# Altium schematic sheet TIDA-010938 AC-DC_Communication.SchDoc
size 431 x 279 mm; Date: Not shown in title block; ApprovedBy: Not shown in title block; CheckedBy: Not shown in title block; Author: Not shown in title block; CompanyName: Not shown in title block; Engineer: Not shown in title block; Organization: Not shown in title block; Address1: Not shown in title block; Address2: Not shown in title block; Address3: Not shown in title block; Address4: Not shown in title block; DocumentNumber: 10; Revision: Use project parameter SCH_Rev; SheetNumber: 10; SheetTotal: 11; PageSetup: Record=PageOptions¦CenterHorizontal=True¦CenterVertical=True¦PrintScale=1.00¦XCorrection=1.00¦YCorrection=1.00¦PrintKind=0¦BorderSize=5000000¦LeftOffset=0¦BottomOffset=0¦Orientation=2¦PaperLength=1000¦PaperWidth=1000¦Scale=100¦PaperSource=15¦PrintQuality=600¦MediaType=1¦DitherType=10¦PaperKind=Letter¦PrintScaleMode=1
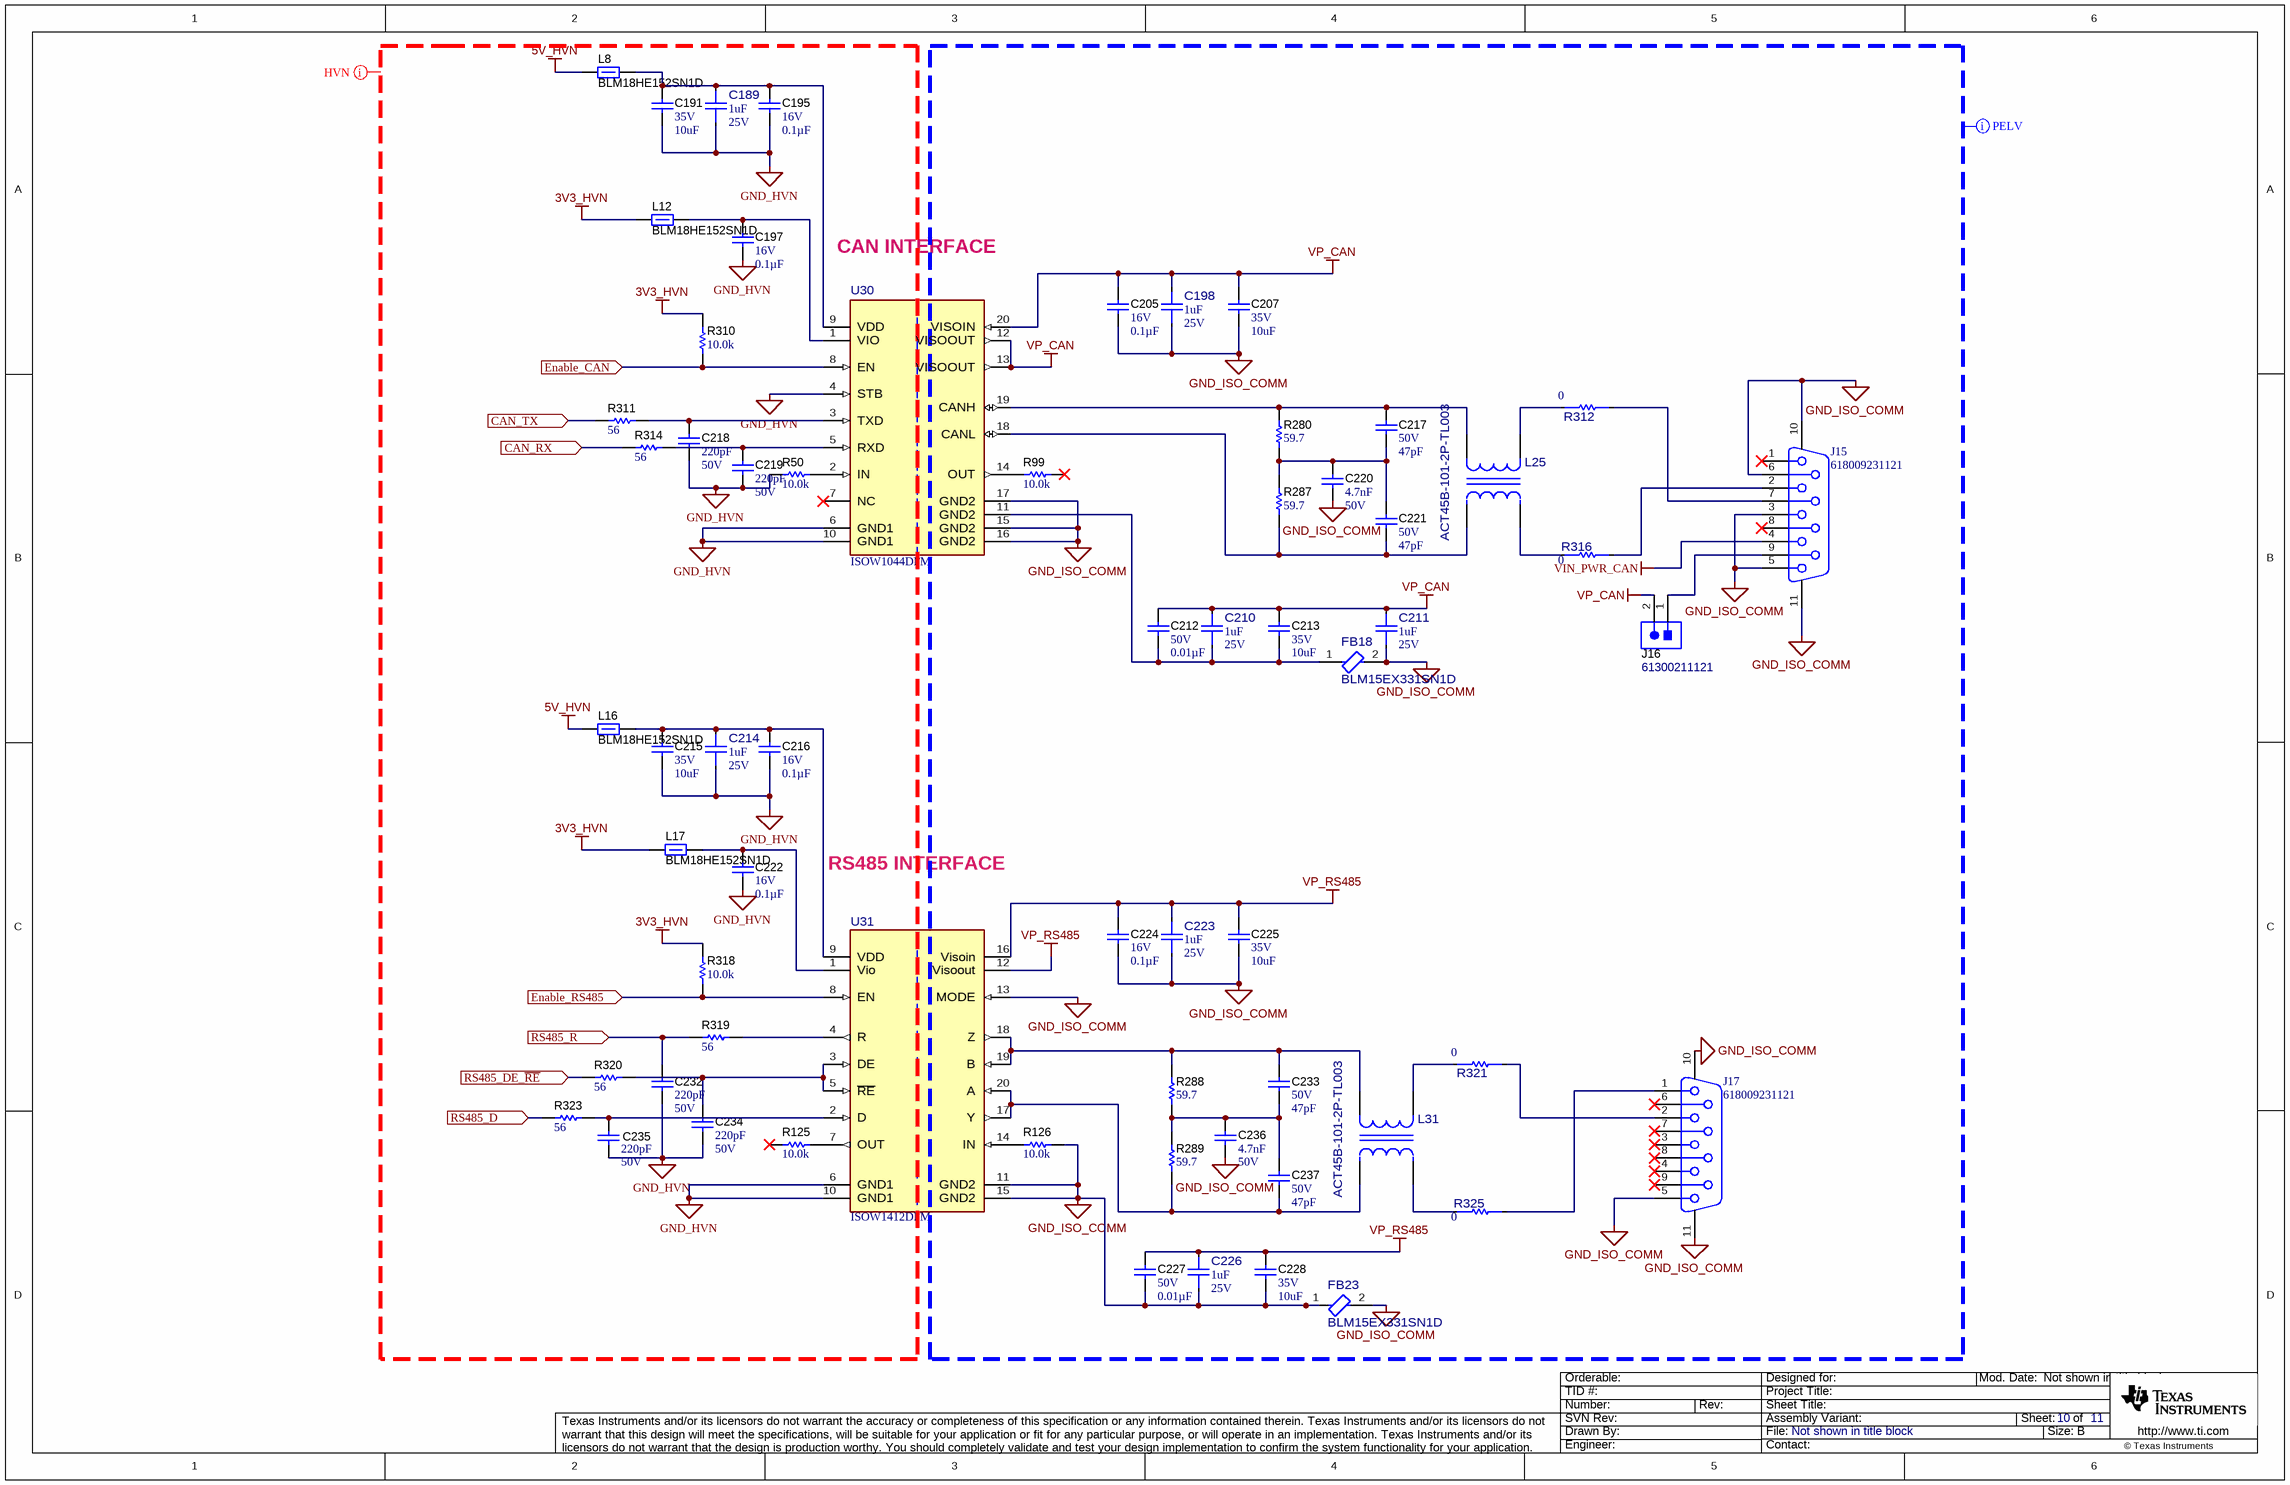
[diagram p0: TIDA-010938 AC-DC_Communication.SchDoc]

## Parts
C189  ValueDisplayed: 1uF  VDC_V: 25V  [FP-CL10A105KA8NNNC_0603-IPC_C]  (hidden comment: CL10A105KA8NNNC)
C191  VDC_V: 35V  ValueDisplayed: 10uF  [0805_HV]  (hidden comment: GRM21BR6YA106KE43L)
C195  VDC_V: 16V  ValueDisplayed: 0.1µF  [0402]  (hidden comment: CL05B104KO5NNNC)
C197  VDC_V: 16V  ValueDisplayed: 0.1µF  [0402]  (hidden comment: CL05B104KO5NNNC)
C198  ValueDisplayed: 1uF  VDC_V: 25V  [FP-CL10A105KA8NNNC_0603-IPC_C]  (hidden comment: CL10A105KA8NNNC)
C205  VDC_V: 16V  ValueDisplayed: 0.1µF  [0402]  (hidden comment: CL05B104KO5NNNC)
C207  VDC_V: 35V  ValueDisplayed: 10uF  [0805_HV]  (hidden comment: GRM21BR6YA106KE43L)
C210  ValueDisplayed: 1uF  VDC_V: 25V  [FP-CL10A105KA8NNNC_0603-IPC_C]  (hidden comment: CL10A105KA8NNNC)
C211  ValueDisplayed: 1uF  VDC_V: 25V  [FP-CL10A105KA8NNNC_0603-IPC_C]  (hidden comment: CL10A105KA8NNNC)
C212  VDC_V: 50V  ValueDisplayed: 0.01µF  [0402]  (hidden comment: 0402B103K500CT)
C213  VDC_V: 35V  ValueDisplayed: 10uF  [0805_HV]  (hidden comment: GRM21BR6YA106KE43L)
C214  ValueDisplayed: 1uF  VDC_V: 25V  [FP-CL10A105KA8NNNC_0603-IPC_C]  (hidden comment: CL10A105KA8NNNC)
C215  VDC_V: 35V  ValueDisplayed: 10uF  [0805_HV]  (hidden comment: GRM21BR6YA106KE43L)
C216  VDC_V: 16V  ValueDisplayed: 0.1µF  [0402]  (hidden comment: CL05B104KO5NNNC)
C217  VDC_V: 50V  ValueDisplayed: 47pF  [0603]  (hidden comment: GRM1885C1H470JA01D)
C218  Cap_F: 220pF  VDC_V: 50V  [0603]  (hidden comment: GRM188R71H221KA01D)
C219  Cap_F: 220pF  VDC_V: 50V  [0603]  (hidden comment: GRM188R71H221KA01D)
C220  Cap_F: 4.7nF  VDC_V: 50V  [0603]  (hidden comment: C0603X472K5RACTU)
C221  VDC_V: 50V  ValueDisplayed: 47pF  [0603]  (hidden comment: GRM1885C1H470JA01D)
C222  VDC_V: 16V  ValueDisplayed: 0.1µF  [0402]  (hidden comment: CL05B104KO5NNNC)
C223  ValueDisplayed: 1uF  VDC_V: 25V  [FP-CL10A105KA8NNNC_0603-IPC_C]  (hidden comment: CL10A105KA8NNNC)
C224  VDC_V: 16V  ValueDisplayed: 0.1µF  [0402]  (hidden comment: CL05B104KO5NNNC)
C225  VDC_V: 35V  ValueDisplayed: 10uF  [0805_HV]  (hidden comment: GRM21BR6YA106KE43L)
C226  ValueDisplayed: 1uF  VDC_V: 25V  [FP-CL10A105KA8NNNC_0603-IPC_C]  (hidden comment: CL10A105KA8NNNC)
C227  VDC_V: 50V  ValueDisplayed: 0.01µF  [0402]  (hidden comment: 0402B103K500CT)
C228  VDC_V: 35V  ValueDisplayed: 10uF  [0805_HV]  (hidden comment: GRM21BR6YA106KE43L)
C232  Cap_F: 220pF  VDC_V: 50V  [0603]  (hidden comment: GRM188R71H221KA01D)
C233  VDC_V: 50V  ValueDisplayed: 47pF  [0603]  (hidden comment: GRM1885C1H470JA01D)
C234  Cap_F: 220pF  VDC_V: 50V  [0603]  (hidden comment: GRM188R71H221KA01D)
C235  Cap_F: 220pF  VDC_V: 50V  [0603]  (hidden comment: GRM188R71H221KA01D)
C236  Cap_F: 4.7nF  VDC_V: 50V  [0603]  (hidden comment: C0603X472K5RACTU)
C237  VDC_V: 50V  ValueDisplayed: 47pF  [0603]  (hidden comment: GRM1885C1H470JA01D)
FB18  BLM15EX331SN1D  [FP-BLM15EX331SN1D_0402-MFG]
FB23  BLM15EX331SN1D  [FP-BLM15EX331SN1D_0402-MFG]
J15  618009231121  [Wurth_618009231121]
J16  61300211121  [WURTH_61300211121]
J17  618009231121  [Wurth_618009231121]
L8  BLM18HE152SN1D  [0603]
L12  BLM18HE152SN1D  [0603]
L16  BLM18HE152SN1D  [0603]
L17  BLM18HE152SN1D  [0603]
L25  ACT45B-101-2P-TL003  [FP-ACT45B-101-2P-TL003_SMT_4MM5_3MM2-MFG]
L31  ACT45B-101-2P-TL003  [FP-ACT45B-101-2P-TL003_SMT_4MM5_3MM2-MFG]
R50  ValueDisplayed: 10.0k  [0603]  (hidden comment: RG1608P-103-B-T5)
R99  ValueDisplayed: 10.0k  [0603]  (hidden comment: RG1608P-103-B-T5)
R125  ValueDisplayed: 10.0k  [0603]  (hidden comment: RG1608P-103-B-T5)
R126  ValueDisplayed: 10.0k  [0603]  (hidden comment: RG1608P-103-B-T5)
R280  ValueDisplayed: 59.7  [0603]  (hidden comment: RT0603DRE0759R7L)
R287  ValueDisplayed: 59.7  [0603]  (hidden comment: RT0603DRE0759R7L)
R288  ValueDisplayed: 59.7  [0603]  (hidden comment: RT0603DRE0759R7L)
R289  ValueDisplayed: 59.7  [0603]  (hidden comment: RT0603DRE0759R7L)
R310  ValueDisplayed: 10.0k  [0603]  (hidden comment: RG1608P-103-B-T5)
R311  ValueDisplayed: 56  [0603]  (hidden comment: RG1608P-560-B-T5)
R312  Res_ohm: 0  [FP-RMCF0805ZT0R00_0805-MFG]  (hidden comment: RMCF0805ZT0R00)
R314  ValueDisplayed: 56  [0603]  (hidden comment: RG1608P-560-B-T5)
R316  Res_ohm: 0  [FP-RMCF0805ZT0R00_0805-MFG]  (hidden comment: RMCF0805ZT0R00)
R318  ValueDisplayed: 10.0k  [0603]  (hidden comment: RG1608P-103-B-T5)
R319  ValueDisplayed: 56  [0603]  (hidden comment: RG1608P-560-B-T5)
R320  ValueDisplayed: 56  [0603]  (hidden comment: RG1608P-560-B-T5)
R321  Res_ohm: 0  [FP-RMCF0805ZT0R00_0805-MFG]  (hidden comment: RMCF0805ZT0R00)
R323  ValueDisplayed: 56  [0603]  (hidden comment: RG1608P-560-B-T5)
R325  Res_ohm: 0  [FP-RMCF0805ZT0R00_0805-MFG]  (hidden comment: RMCF0805ZT0R00)
U30  ISOW1044DFM  [DFM0020A-MFG]
U31  ISOW1412DFM  [DFM0020A-MFG]

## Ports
CAN_RX (in), CAN_TX (in), Enable_CAN (in), Enable_RS485 (in), RS485_D (in), RS485_DE_~{RE} (in), RS485_R (in)

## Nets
3V3_HVN: L12.1 L17.1 R310.2 R318.2
5V_HVN: L8.1 L16.1
GND_HVN: C189.1 C191.2 C195.2 C197.2 C214.1 C215.2 C216.2 C218.1 C219.1 C222.2 C232.1 C234.1 C235.1 R50.2 U30.4(STB) U30.6(GND1) U30.10(GND1) U31.6(GND1) U31.10(GND1)
GND_ISO_COMM: C198.1 C205.2 C207.2 C211.1 C220.1 C223.1 C224.2 C225.2 C226.1 C227.2 C228.2 C236.1 FB18.2 FB23.1 FB23.2 J15.3 J15.5 J15.6 J15.10 J15.11 J17.5 J17.10 J17.11 R126.1 U30.15(GND2) U30.16(GND2) U30.17(GND2) U31.11(GND2) U31.13(MODE) U31.15(GND2)
VIN_PWR_CAN: J15.4
VP_CAN: C198.2 C205.1 C207.1 C210.2 C211.2 C212.1 C213.1 J16.2 U30.12(VISOOUT) U30.13(VISOOUT) U30.20(VISOIN)
VP_RS485: C223.2 C224.1 C225.1 C226.2 C227.1 C228.1 U31.12(Visoout) U31.16(Visoin)
CAN_RX: R314.1 ; port CAN_RX
CAN_TX: R311.1 ; port CAN_TX
Enable_CAN: R310.1 U30.8(EN) ; port Enable_CAN
Enable_RS485: R318.1 U31.8(EN) ; port Enable_RS485
RS485_D: R323.1 ; port RS485_D
RS485_DE_~{RE}: R320.1 ; port RS485_DE_~{RE}
RS485_R: C232.2 R319.1 ; port RS485_R
NetC189_2: C189.2 C191.1 C195.1 L8.2 U30.9(VDD)
NetC197_1: C197.1 L12.2 U30.1(VIO)
NetC210_1: C210.1 C212.2 C213.2 FB18.1 U30.11(GND2)
NetC214_2: C214.2 C215.1 C216.1 L16.2 U31.9(VDD)
NetC217_1: C217.1 C220.2 C221.2 R280.1 R287.2
NetC217_2: C217.2 L25.1 R280.2 U30.19(CANH)
NetC218_2: C218.2 R311.2 U30.3(TXD)
NetC219_2: C219.2 R314.2 U30.5(RXD)
NetC221_1: C221.1 L25.2 R287.1 U30.18(CANL)
NetC222_1: C222.1 L17.2 U31.1(Vio)
NetC233_1: C233.1 C236.2 C237.2 R288.1 R289.2
NetC233_2: C233.2 L31.1 R288.2 U31.18(Z) U31.19(B)
NetC234_2: C234.2 R320.2 U31.3(DE) U31.5(~{RE})
NetC235_2: C235.2 R323.2 U31.2(D)
NetC237_1: C237.1 L31.2 R289.1 U31.17(Y) U31.20(A)
NetJ15_2: J15.2 R316.2
NetJ15_7: J15.7 R312.2
NetJ15_9: J15.9 J16.1
NetJ17_1: J17.1 R325.2
NetJ17_2: J17.2 R321.2
NetL25_3: L25.3 R316.1
NetL25_4: L25.4 R312.1
NetL31_3: L31.3 R325.1
NetL31_4: L31.4 R321.1
NetR50_1: R50.1 U30.2(IN)
NetR99_2: R99.2 U30.14(OUT)
NetR125_1: R125.1 U31.7(OUT)
NetR126_2: R126.2 U31.14(IN)
NetR319_2: R319.2 U31.4(R)

Not connected (* = marked no-connect by the designer): J15 1* 8*; J17 3* 4* 6* 7* 8* 9*; R99 1*; R125 2*; U30 7(NC)*

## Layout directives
net class HVN: 3V3_HVN, 5V_HVN, GND_HVN
net class PELV: GND_ISO_COMM, VIN_PWR_CAN, VP_CAN, VP_RS485

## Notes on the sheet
- CAN INTERFACE
- RS485 INTERFACE

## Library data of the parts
C189 C198 C210 C211 C214 C223 C226 = CMP-0094926-1: Cap Ceramic 1uF 25V X5R ±10% Pad SMD 0603 +85°C T/R; Manufacturer: Samsung; TempCo: 0.15; AEC Qualified: No; Cap_F: 1µF; Value: 1µF; SizeZ_mm: 0.9mm
C191 C207 C213 C215 C225 C228 = CMP-0008310-2: CAP, CERM, 10 uF, 35 V, +/- 10%, X5R, 0805; Manufacturer: MuRata; TaMin_C: -55°C; Polarized: N; SizeAreaWB_mm2: 6.75; Value1: Unknown; U/M: EA; Value: 10uF; TaMax_C: 85°C; SizeZ_mm: 1.45; SizeX_mm: 2; SizeY_mm: 1.25; Cap_Case: 0805; SizeArea_mm2: 2.5; Cap_F: 10µF; AEC Category: Q200
C195 C197 C205 C216 C222 C224 = CMP-0085850-1: CAP, CERM, 0.1 µF, 16 V,+/- 10%, X7R, 0402; Manufacturer: Walsin; SizeZ_mm: 0.6; SizeX_mm: 1; AEC Category: Q200; AEC Qualified: N; SizeY_mm: 0.5; Value: 0.1uF; Cap_F: 100nF; U/M: EA; SizeAreaWB_mm2: 3; TaMin_C: -55°C; TaMax_C: 125°C
C212 C227 = CMP-0085842-1: CAP, CERM, 0.01 µF, 50 V,+/- 10%, X7R, 0402; Manufacturer: Walsin; AEC Qualified: N; SizeZ_mm: 0.6; U/M: EA; Value: 0.01uF; TaMax_C: 125°C; AEC Category: Q200; SizeY_mm: 0.5; Cap_F: 10nF; SizeAreaWB_mm2: 3; TaMin_C: -55°C; SizeX_mm: 1
C217 C221 C233 C237 = CMP-0007220-4: CAP, CERM, 47 pF, 50 V, +/- 5%, C0G/NP0, 0603; Manufacturer: MuRata; TaMin_C: -55°C; Polarized: N; SizeAreaWB_mm2: 4.68; Value1: Unknown; U/M: EA; Value: 47pF; TaMax_C: 125°C; SizeZ_mm: 1; SizeX_mm: 1.6; SizeY_mm: 0.8; SizeArea_mm2: 1.28; AEC Category: Q200
C218 C219 C232 C234 C235 = CMP-0007442-5: CAP, CERM, 220 pF, 50 V, +/- 10%, X7R, 0603; Manufacturer: MuRata; TaMin_C: -55°C; Polarized: N; SizeAreaWB_mm2: 4.68; Value1: Unknown; U/M: EA; Value: 220pF; TaMax_C: 125°C; SizeZ_mm: 1; SizeX_mm: 1.6; SizeY_mm: 0.8; SizeArea_mm2: 1.28; AEC Category: Q200
C220 C236 = CMP-0006987-4: CAP, CERM, 4700 pF, 50 V, +/- 10%, X7R, 0603; Manufacturer: Kemet; TaMin_C: -55°C; Polarized: N; SizeAreaWB_mm2: 4.68; Value1: Unknown; U/M: EA; Value: 4700pF; TaMax_C: 125°C; SizeZ_mm: 1; SizeX_mm: 1.6; SizeY_mm: 0.8; SizeArea_mm2: 1.28; AEC Category: Q200
FB18 FB23 = CMP-0041881-1: Chip Ferrite Bead, 0402, 330Ω @ 100MHz, 0.205Ω, 25%, 1.1A; Manufacturer: Murata; DCR_ohm: 0.205; SizeZ_mm: 0.55mm; AEC Qualified: No; Ciiva Ids: 2806665; Import Ts: 1521856324
J15 J17 = CMP-0054820-2: Receptacle, D-Sub, 9 Position, R/A, TH; Manufacturer: Wurth Elektronik; Pitch_mm: 2.77; Gender: Female; Cert_UL: Y; Voltage_V: 125V; ContactFinish: Gold; Row_Count: 2; Current_A: 3A; CNHeader: FALSE; CT: TRUE
J16 = CMP-0054794-2: Header, 2.54 mm, 2x1, Gold, TH; Manufacturer: Wurth Elektronik; Green_Lifecycle: Active; Green_REACh: Passed; Cert_UL: Y; Gender: Male; Pitch_mm: 2.54; Row_Count: 1; Shrouded: N
L8 L12 L16 L17 = CMP-0003349-2: Ferrite Bead, 1500 ohm @ 100 MHz, 0.5 A, 0603; Manufacturer: MuRata; Ztyp@1GHz_Ohm: 1.5k; SizeAreaWB_mm2: 4.68; DCR_ohm: 5d; Value1: 0.5 ohm; Imax_A: 5dA; SizeZ_mm: 1; SizeX_mm: 1.6; SizeY_mm: 0.8; Value2: 0.5A; SizeArea_mm2: 1.28
L25 L31 = CMP-0084086-1: 100µH @ 100kHz 2 Line Common Mode Choke Surface Mount 5.8 kOhms @ 10MHz 150mA DCR 2Ohm; Manufacturer: TDK; AEC Grade: Grade 0; Tolerance_%: +50/-30%; AEC Qualified: Yes; Ind_H: 100uH; SizeZ_mm: 3mm; DCR_ohm: 2Ω; Impedance At Frequency: 5800Ω @ 10MHz; Imax_A: 0.15A
R50 R99 R125 R126 R310 R318 = CMP-0023404-3: RES, 10.0 k, 0.1%, 0.1 W, 0603; Manufacturer: Susumu Co Ltd; Power_W: 100mW; TempCo: 25 ppm/C; Value_Code: 10k0; U/M: EA; Value: 10.0k; EIA_Code: E192; Res_ohm: 10k; SizeX_mm: 1.6; SizeY_mm: 0.8; SizeZ_mm: 1; Value2: 0.1W; SizeArea_mm2: 1.28; VDC_V: 75V; AEC Category: Q200
R280 R287-R289 = CMP-0025431-3: RES, 59.7, 0.5%, 0.1 W, 0603; Manufacturer: Yageo America; Power_W: 100mW; TempCo: 50 ppm/C; Value_Code: 59R7; U/M: EA; Value: 59.7; EIA_Code: E192; SizeX_mm: 1.6; SizeY_mm: 0.8; SizeZ_mm: 1; Value2: 0.1W; SizeArea_mm2: 1.28; VDC_V: 75V; AEC Category: Q200
R311 R314 R319 R320 R323 = CMP-0023572-3: RES, 56, 0.1%, 0.1 W, 0603; Manufacturer: Susumu Co Ltd; Power_W: 100mW; TempCo: 25 ppm/C; Value_Code: 56R0; U/M: EA; Value: 56; SizeX_mm: 1.6; SizeY_mm: 0.8; SizeZ_mm: 1; Value2: 0.1W; SizeArea_mm2: 1.28; VDC_V: 75V; AEC Category: Q200
R312 R316 R321 R325 = CMP-0089632-1: 0 Ohms Jumper 0.125W, 1/8W Chip Resistor 0805 (2012 Metric) Automotive AEC-Q200 Thick Film; Manufacturer: Stackpole Electronics; TempCo: 200ppm/°C; SizeZ_mm: 0.65mm; AEC Grade: Grade 0; AEC Qualified: Yes; Power_W: 125mW; VDC_V: 150V
U30 = CMP-0092023-2: Reinforced 5-kVRMS Isolated CAN Transceiver with Integrated lowemissions DC-DC Converter; Manufacturer: Texas Instruments; TJmax_C: +150°C; Max Supply Voltage: 5.5V; AEC Qualified: No; Standoff Height: 0.1mm; Nominal Supply Current: 0.3-124mA; CompType: IC; AEC Category: Q200; TaMax_C: +105°C; SizeZ_mm: 3.55mm; Min Supply Voltage: 1.71V; TaMin_C: -40°C
U31 = CMP-0089988-1: Reinforced 5-kVRMS Isolated RS-485/RS-422 Transceiver With Integrated Low Emissions DC-DC Converter; Manufacturer: Texas Instruments; Simplex Duplex: Full-Duplex; Number Of Transmitters: 1; Data Rate: 500kbits/s; Min Supply Voltage: 1.71V; Interface: RS-485,RS-422; Max Supply Voltage: 5.5V; Standoff Height: 0.1mm; TaMax_C: +105°C; TJmax_C: +150°C; TaMin_C: -40°C; AEC Qualified: No; SizeZ_mm: 3.55mm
